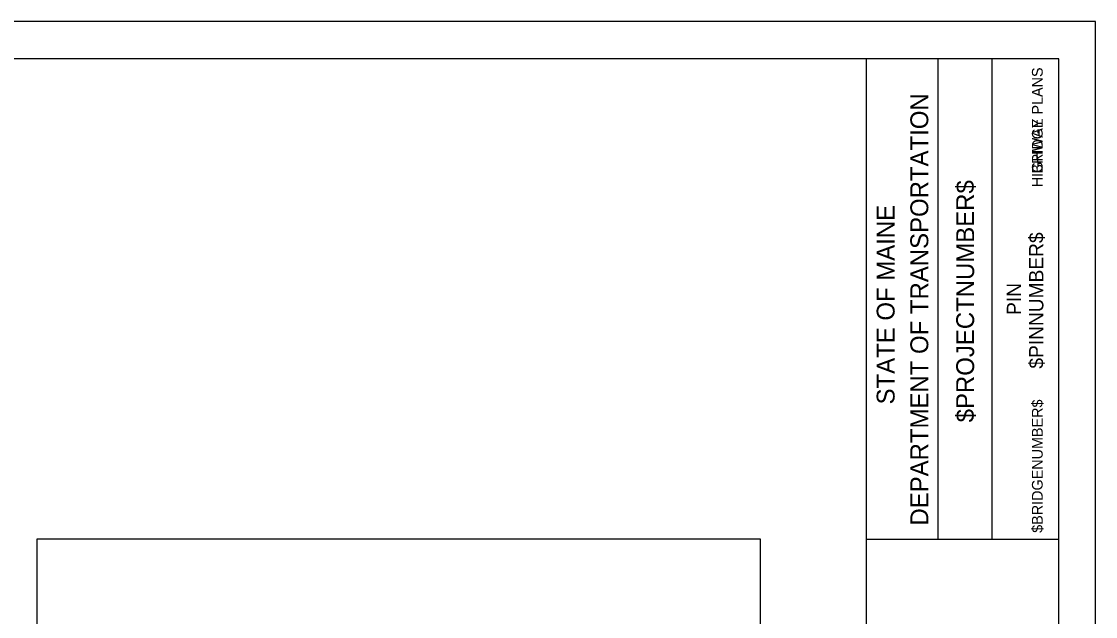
# Model space of a CAD drawing. Extents: x 1100953.92 to 1100956.78, y 416755.57 to 416757.4.
# Drawn here: x 1100955.822 to 1100956.753, y 416756.888 to 416757.404 of the extents above; entities that cross this region are included whole.
import ezdxf

# ---------------------------------------------------------------- set-up
doc = ezdxf.new("R2010")
doc.units = 0
for name, color, linetype in [('BORDER', 7, 'Continuous'), ('BRIDGE_TITLE', 7, 'Continuous'), ('HIGHWAY_TITLE', 7, 'Continuous'), ('ORIG TOPO TEXT', 7, 'Continuous'), ('PLOT BOUNDARY', 7, 'Continuous')]:
    doc.layers.add(name, color=color, linetype=linetype)

msp = doc.modelspace()

# ---------------------------------------------------------------- linework, layer by layer
at = {"layer": 'BORDER'}
for p, q in [((1100956.72159, 416757.37167), (1100954.05493, 416757.37167)), ((1100956.55493, 416755.62172), (1100956.55493, 416757.37172)), ((1100956.61707, 416756.95495), (1100956.61707, 416757.37162)), ((1100956.66365, 416756.95495), (1100956.66365, 416757.37162)), ((1100956.72159, 416755.62172), (1100956.72159, 416757.37172)), ((1100956.55494, 416756.9549), (1100956.72159, 416756.9549))]:
    msp.add_line(p, q, dxfattribs=at)
at = {"layer": 'ORIG TOPO TEXT'}
msp.add_lwpolyline([(1100955.83565, 416756.95507), (1100955.83565, 416756.3569), (1100956.46304, 416756.3569), (1100956.46304, 416756.95507), (1100955.83565, 416756.95507)], dxfattribs=at)
at = {"layer": 'PLOT BOUNDARY'}
msp.add_lwpolyline([(1100953.92004, 416755.57068), (1100956.75337, 416755.57068), (1100956.75337, 416757.40402), (1100953.92004, 416757.40402)], close=True, dxfattribs=at)

# ---------------------------------------------------------------- texts
at = {"layer": 'BORDER'}
for s, height, p in [('DEPARTMENT OF TRANSPORTATION', 0.0155293, (1100956.60837, 416756.96677)), ('$PROJECTNUMBER$', 0.0155293, (1100956.64813, 416757.05632)), ('STATE OF MAINE', 0.0155293, (1100956.57918, 416757.07187)), ('$PINNUMBER$', 0.0124212, (1100956.70819, 416757.10292)), ('PIN', 0.012421, (1100956.68887, 416757.14951))]:
    msp.add_text(s, height=height, rotation=90, dxfattribs=at).set_placement(p)
at = {"layer": 'BRIDGE_TITLE'}
for s, p in [('BRIDGE PLANS', (1100956.70757, 416757.27207)), ('$BRIDGENUMBER$', (1100956.70757, 416756.9605))]:
    msp.add_text(s, height=0.0093168, rotation=90, dxfattribs=at).set_placement(p)
at = {"layer": 'HIGHWAY_TITLE'}
msp.add_text('HIGHWAY PLANS', height=0.0093168, rotation=90, dxfattribs=at).set_placement((1100956.70757, 416757.26026))

doc.saveas('drawing.dxf')
